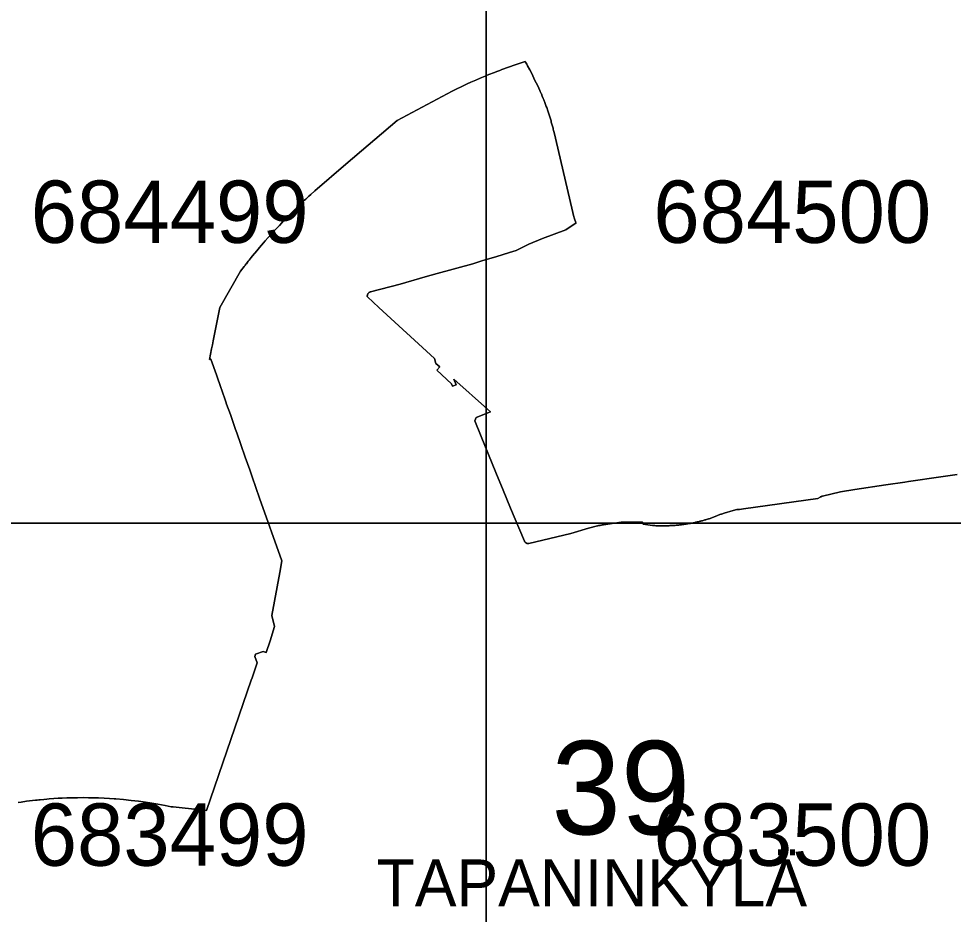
# Model space of a CAD drawing. Extents: x 25485000 to 25520000, y 6656775 to 6690000.
# Drawn here: x 25499249 to 25500750, y 6683372 to 6684810 of the extents above; entities that cross this region are included whole.
import ezdxf

# ---------------------------------------------------------------- set-up
doc = ezdxf.new("R2010")
doc.units = 0
doc.layers.add('Level 63', color=7, linetype='Continuous')

msp = doc.modelspace()

# ---------------------------------------------------------------- linework, layer by layer
at = {"layer": 'Level 63'}
for points in [[(25499000, 6684000), (25500000, 6684000), (25500000, 6685000), (25499000, 6685000)], [(25500000, 6684000), (25501000, 6684000), (25501000, 6685000), (25500000, 6685000)], [(25499000, 6683000), (25500000, 6683000), (25500000, 6684000), (25499000, 6684000)], [(25500000, 6683000), (25501000, 6683000), (25501000, 6684000), (25500000, 6684000)]]:
    msp.add_lwpolyline(points, close=True, dxfattribs=at)
for points in [[(25500756.5, 6684078.4), (25500730.4, 6684074.3), (25500678.5, 6684066.7), (25500672.5, 6684065.8), (25500641.9, 6684061.3), (25500591.9, 6684053.9), (25500569.2, 6684050.4), (25500539.9, 6684043.5), (25500539.6, 6684043.4), (25500539.4, 6684043.2), (25500539.1, 6684043.1), (25500538.9, 6684043), (25500538.6, 6684042.8), (25500538.4, 6684042.7), (25500538.1, 6684042.6), (25500537.9, 6684042.5), (25500537.6, 6684042.4), (25500537.3, 6684042.3), (25500537.1, 6684042.2), (25500536.8, 6684042.1), (25500536.5, 6684042.1), (25500536.2, 6684042), (25500532.5, 6684039.5), (25500413.5, 6684023), (25500406.8, 6684022.1), (25500402.8, 6684021.9), (25500396.5, 6684020.1), (25500382.2, 6684016), (25500380.8, 6684015.6), (25500379.5, 6684015.1), (25500378.1, 6684014.6), (25500376.8, 6684014.2), (25500375.5, 6684013.7), (25500374.2, 6684013.2), (25500372.8, 6684012.7), (25500371.5, 6684012.2), (25500370.2, 6684011.7), (25500368.9, 6684011.2), (25500367.6, 6684010.7), (25500366.2, 6684010.1), (25500364.9, 6684009.6), (25500363.6, 6684009), (25500362.2, 6684008.4), (25500360.9, 6684008), (25500359.6, 6684007.6), (25500358.2, 6684007.1), (25500356.9, 6684006.7), (25500355.5, 6684006.3), (25500354.1, 6684005.9), (25500352.8, 6684005.5), (25500351.4, 6684005.1), (25500350.1, 6684004.7), (25500348.7, 6684004.4), (25500347.3, 6684004), (25500346, 6684003.6), (25500344.6, 6684003.3), (25500343.2, 6684003), (25500341.9, 6684002.6), (25500340.5, 6684002.3), (25500339.1, 6684002), (25500337.7, 6684001.7), (25500336.3, 6684001.4), (25500335, 6684001.1), (25500333.6, 6684000.8), (25500332.2, 6684000.5), (25500330.8, 6684000.2), (25500329.4, 6684000), (25500328, 6683999.7), (25500326.6, 6683999.5), (25500325.2, 6683999.2), (25500323.8, 6683999), (25500322.4, 6683998.8), (25500321, 6683998.5), (25500319.6, 6683998.3), (25500319.1, 6683998.3), (25500317.7, 6683998.1), (25500316.3, 6683997.9), (25500314.9, 6683997.7), (25500313.5, 6683997.5), (25500312.1, 6683997.3), (25500310.6, 6683997.2), (25500309.2, 6683997), (25500307.8, 6683996.9), (25500306.4, 6683996.8), (25500305, 6683996.6), (25500303.6, 6683996.5), (25500302.2, 6683996.4), (25500300.8, 6683996.3), (25500299.4, 6683996.2), (25500298, 6683996.1), (25500296.6, 6683996), (25500295.1, 6683996), (25500293.7, 6683995.9), (25500292.3, 6683995.9), (25500290.9, 6683995.8), (25500289.5, 6683995.8), (25500288.1, 6683995.7), (25500286.7, 6683995.7), (25500285.2, 6683995.7), (25500283.8, 6683995.7), (25500282.4, 6683995.7), (25500281, 6683995.7), (25500279.6, 6683995.7), (25500278.2, 6683995.8), (25500276.8, 6683995.8), (25500275.4, 6683995.8), (25500273.9, 6683995.9), (25500272.5, 6683995.9), (25500271.1, 6683996), (25500269.7, 6683996.1), (25500268.3, 6683996.2), (25500267.2, 6683996.2), (25500252.4, 6683998.4), (25500251.1, 6684001.7), (25500243, 6684001.7), (25500233, 6684001.5), (25500217, 6684001.4), (25500188.6, 6683997.4), (25500187.5, 6683997.2), (25500186.3, 6683997.1), (25500185.2, 6683996.9), (25500184, 6683996.7), (25500182.9, 6683996.5), (25500181.7, 6683996.3), (25500180.6, 6683996.1), (25500179.5, 6683995.8), (25500178.8, 6683995.7), (25500164.1, 6683992), (25500136, 6683983.6), (25500068.5, 6683967.5), (25500068.2, 6683967.5), (25500068, 6683967.4), (25500067.8, 6683967.4), (25500067.6, 6683967.4), (25500067.4, 6683967.4), (25500067.2, 6683967.4), (25500066.9, 6683967.4), (25500066.7, 6683967.4), (25500066.5, 6683967.4), (25500066.3, 6683967.4), (25500066.1, 6683967.5), (25500065.8, 6683967.5), (25500065.6, 6683967.5), (25500065.4, 6683967.6), (25500065.2, 6683967.7), (25500065, 6683967.7), (25500064.8, 6683967.8), (25500064.6, 6683967.9), (25500064.4, 6683968), (25500064.2, 6683968.1), (25500064, 6683968.2), (25500063.8, 6683968.3), (25500063.6, 6683968.4), (25500063.5, 6683968.6), (25500063.3, 6683968.7), (25500063.1, 6683968.8), (25500063, 6683969), (25500062.8, 6683969.1), (25500062.7, 6683969.3), (25500062.5, 6683969.5), (25500062.4, 6683969.6), (25500062.2, 6683969.8), (25500062.1, 6683970), (25500062, 6683970.2), (25500061.9, 6683970.4), (25500061.8, 6683970.5), (25500061.7, 6683970.7), (25500061.6, 6683970.9), (25500061.5, 6683971.1), (25500039.3, 6684024), (25500027.5, 6684052.8), (25500015.7, 6684081.4), (25500004, 6684110.2), (25499992.2, 6684139.2), (25499981.8, 6684164.5), (25499984, 6684169.8), (25500007.1, 6684178.5), (25500002, 6684183.1), (25499947.8, 6684231.4), (25499951.6, 6684222), (25499946.1, 6684219.7), (25499944.5, 6684223.7), (25499920.8, 6684245.6), (25499925.8, 6684250.9), (25499919.2, 6684256.6), (25499916.8, 6684264.6), (25499827.8, 6684346.2), (25499809.2, 6684363.2), (25499809.2, 6684363.5), (25499809.1, 6684363.7), (25499809.1, 6684363.9), (25499809.1, 6684364.2), (25499809.1, 6684364.4), (25499809.1, 6684364.6), (25499809.1, 6684364.9), (25499809.1, 6684365.1), (25499809.1, 6684365.4), (25499809.2, 6684365.6), (25499809.2, 6684365.8), (25499809.2, 6684366.1), (25499809.3, 6684366.3), (25499809.4, 6684366.5), (25499809.4, 6684366.7), (25499809.5, 6684367), (25499809.6, 6684367.2), (25499809.7, 6684367.4), (25499809.8, 6684367.6), (25499809.9, 6684367.8), (25499810, 6684368), (25499810.1, 6684368.2), (25499810.2, 6684368.4), (25499810.4, 6684368.6), (25499810.5, 6684368.8), (25499810.7, 6684369), (25499810.8, 6684369.2), (25499811, 6684369.4), (25499811.1, 6684369.5), (25499811.3, 6684369.7), (25499811.5, 6684369.9), (25499811.7, 6684370), (25499811.8, 6684370.2), (25499812, 6684370.3), (25499812.2, 6684370.4), (25499812.4, 6684370.6), (25499812.6, 6684370.7), (25499812.8, 6684370.8), (25499813.1, 6684370.9), (25499813.3, 6684371), (25499813.5, 6684371.1), (25499813.7, 6684371.2), (25499813.9, 6684371.3), (25499814.2, 6684371.3), (25499814.3, 6684371.4), (25499861.7, 6684383.9), (25499902, 6684395.7), (25499921.2, 6684401), (25499978.6, 6684416.6), (25499994.7, 6684421.5), (25500015.4, 6684427.4), (25500037.7, 6684434.4), (25500048.2, 6684437.8), (25500068.7, 6684447.7), (25500090.3, 6684456.9), (25500127.9, 6684471.1), (25500144.7, 6684482), (25500144.4, 6684482.4), (25500144.2, 6684482.9), (25500143.9, 6684483.4), (25500143.7, 6684483.9), (25500143.5, 6684484.4), (25500143.2, 6684484.8), (25500143, 6684485.3), (25500142.8, 6684485.9), (25500142.6, 6684486.4), (25500142.4, 6684486.9), (25500142.2, 6684487.4), (25500142, 6684487.9), (25500141.9, 6684488.4), (25500141.7, 6684488.9), (25500141.5, 6684489.4), (25500141.4, 6684490), (25500141.2, 6684490.5), (25500141.1, 6684491), (25500141, 6684491.6), (25500137.6, 6684505.8), (25500109, 6684627.3), (25500108.6, 6684629), (25500108.2, 6684630.6), (25500107.8, 6684632.3), (25500107.4, 6684634), (25500106.9, 6684635.7), (25500106.5, 6684637.4), (25500106, 6684639), (25500105.6, 6684640.7), (25500105.1, 6684642.4), (25500104.6, 6684644), (25500104.2, 6684645.7), (25500103.7, 6684647.4), (25500103.2, 6684649), (25500102.7, 6684650.7), (25500102.2, 6684652.3), (25500101.6, 6684654), (25500101.1, 6684655.6), (25500100.6, 6684657.3), (25500100, 6684658.9), (25500099.5, 6684660.6), (25500098.9, 6684662.2), (25500098.4, 6684663.8), (25500097.8, 6684665.5), (25500097.2, 6684667.1), (25500096.6, 6684668.7), (25500096, 6684670.4), (25500095.4, 6684672), (25500094.8, 6684673.6), (25500094.2, 6684675.2), (25500093.6, 6684676.8), (25500093.1, 6684678), (25500093.1, 6684678.1), (25500093, 6684678.3), (25500092.6, 6684679.4), (25500091.7, 6684681.6), (25500090.1, 6684685.5), (25500088.6, 6684689.1), (25500088.2, 6684689.8), (25500088.2, 6684690), (25500086.9, 6684692.8), (25500086.1, 6684694.6), (25500082.8, 6684701.9), (25500080.2, 6684707.1), (25500077.7, 6684712), (25500073.6, 6684720.7), (25500070.2, 6684727.6), (25500066.5, 6684734.4), (25500065.1, 6684737), (25500063.4, 6684740), (25500063.3, 6684740.2), (25500063, 6684740.8), (25500062.6, 6684741.4), (25500046.3, 6684735.6), (25500025.2, 6684728.2), (25500021.9, 6684726.9), (25500018.8, 6684725.8), (25500011.6, 6684723), (25500005.8, 6684720.7), (25500001.8, 6684719), (25499998.2, 6684717.5), (25499990.3, 6684714.3), (25499983.6, 6684711.4), (25499977.9, 6684708.9), (25499975.4, 6684707.8), (25499969.7, 6684705.2), (25499960.7, 6684701.1), (25499951.9, 6684696.9), (25499945.3, 6684693.7), (25499857.1, 6684646.6), (25499774.7, 6684576.3), (25499724.7, 6684533.7), (25499718.4, 6684527.9), (25499715.3, 6684525), (25499715.3, 6684525), (25499715.3, 6684525), (25499715.3, 6684525), (25499714.9, 6684524.6), (25499714.7, 6684524.5), (25499714.5, 6684524.3), (25499714.4, 6684524.2), (25499714.3, 6684524.1), (25499713.9, 6684523.7), (25499713.8, 6684523.6), (25499713.5, 6684523.3), (25499713.1, 6684523), (25499712.6, 6684522.5), (25499712.1, 6684522), (25499711.3, 6684521.3), (25499710.2, 6684520.2), (25499708.1, 6684518.3), (25499701.5, 6684512), (25499700.3, 6684510.7), (25499698.4, 6684509), (25499690, 6684500.7), (25499680.6, 6684491.3), (25499674.7, 6684485.3), (25499671.7, 6684482.2), (25499667.9, 6684478.1), (25499665.3, 6684475.4), (25499660.4, 6684470.2), (25499654.9, 6684464.2), (25499649.8, 6684458.6), (25499645, 6684453.4), (25499642.1, 6684450.1), (25499635.7, 6684442.6), (25499631.4, 6684437.3), (25499624.7, 6684429), (25499622.5, 6684426.3), (25499619.1, 6684422), (25499618.9, 6684421.7), (25499618.5, 6684421.3), (25499617.9, 6684420.5), (25499616.9, 6684419.1), (25499614.9, 6684416.6), (25499614.9, 6684416.6), (25499614.8, 6684416.5), (25499614.8, 6684416.5), (25499614.8, 6684416.5), (25499614.8, 6684416.4), (25499614.7, 6684416.4), (25499614.7, 6684416.3), (25499614.5, 6684416.1), (25499613.1, 6684414.3), (25499612.7, 6684413.8), (25499612, 6684412.8), (25499611.4, 6684412.1), (25499605.6, 6684404.4), (25499572, 6684346.5), (25499561.6, 6684292.8), (25499560.3, 6684286.1), (25499559.1, 6684279.8), (25499555.8, 6684262.8), (25499557.9, 6684263.4), (25499566.8, 6684238.3), (25499574.5, 6684216.1), (25499574.8, 6684215.1), (25499582, 6684194.7), (25499583.2, 6684191.1), (25499589.1, 6684174.2), (25499591.8, 6684166.3), (25499597.5, 6684150.4), (25499599.4, 6684145), (25499605.9, 6684126.1), (25499612.8, 6684106.2), (25499620.2, 6684085.4), (25499624, 6684074.6), (25499636.1, 6684040.1), (25499671.7, 6683939.4), (25499668.4, 6683920.6), (25499656, 6683851.6), (25499660.2, 6683834.1), (25499652.9, 6683811.3), (25499646.4, 6683792.5), (25499641.7, 6683794.1), (25499629.7, 6683789.6), (25499628.4, 6683785.8), (25499632.1, 6683775.9), (25499624.1, 6683751.8), (25499622.6, 6683747.7), (25499550.7, 6683538.5), (25499541.2, 6683539.6), (25499497.1, 6683544.7), (25499493.9, 6683544.8), (25499484.4, 6683546.7), (25499472.9, 6683548.8), (25499462.9, 6683550.5), (25499452.7, 6683552.1), (25499441.7, 6683553.6), (25499429.7, 6683555), (25499417.3, 6683556.3), (25499405.4, 6683557.3), (25499402.3, 6683557.5), (25499395.1, 6683558), (25499386.7, 6683558.5), (25499377.1, 6683558.9), (25499369, 6683559.2), (25499361.5, 6683559.3), (25499353.5, 6683559.4), (25499343.9, 6683559.3), (25499334.9, 6683559.2), (25499330.8, 6683559), (25499326.7, 6683558.9), (25499319.2, 6683558.6), (25499312.6, 6683558.3), (25499305.5, 6683557.8), (25499298, 6683557.3), (25499294.5, 6683557), (25499289.8, 6683556.6), (25499283.8, 6683556), (25499281.7, 6683555.8), (25499278.9, 6683555.5), (25499276.3, 6683555.3), (25499261.8, 6683553.5), (25499253, 6683552.3), (25499248.3, 6683551.6)], [(25499248.3, 6683551.6), (25499253, 6683552.3), (25499261.8, 6683553.5), (25499276.3, 6683555.3), (25499278.9, 6683555.5), (25499281.7, 6683555.8), (25499283.8, 6683556), (25499289.8, 6683556.6), (25499294.5, 6683557), (25499298, 6683557.3), (25499305.5, 6683557.8), (25499312.6, 6683558.3), (25499319.2, 6683558.6), (25499326.7, 6683558.9), (25499330.8, 6683559), (25499334.9, 6683559.2), (25499343.9, 6683559.3), (25499353.5, 6683559.4), (25499361.5, 6683559.3), (25499369, 6683559.2), (25499377.1, 6683558.9), (25499386.7, 6683558.5), (25499395.1, 6683558), (25499402.3, 6683557.5), (25499405.4, 6683557.3), (25499417.3, 6683556.3), (25499429.7, 6683555), (25499441.7, 6683553.6), (25499452.7, 6683552.1), (25499462.9, 6683550.5), (25499472.9, 6683548.8), (25499484.4, 6683546.7), (25499493.9, 6683544.8), (25499497.1, 6683544.7), (25499541.2, 6683539.6), (25499550.7, 6683538.5), (25499622.6, 6683747.7), (25499624.1, 6683751.8), (25499632.1, 6683775.9), (25499628.4, 6683785.8), (25499629.7, 6683789.6), (25499641.7, 6683794.1), (25499646.4, 6683792.5), (25499652.9, 6683811.3), (25499660.2, 6683834.1), (25499656, 6683851.6), (25499668.4, 6683920.6), (25499671.7, 6683939.4), (25499636.1, 6684040.1), (25499624, 6684074.6), (25499620.2, 6684085.4), (25499612.8, 6684106.2), (25499605.9, 6684126.1), (25499599.4, 6684145), (25499597.5, 6684150.4), (25499591.8, 6684166.3), (25499589.1, 6684174.2), (25499583.2, 6684191.1), (25499582, 6684194.7), (25499574.8, 6684215.1), (25499574.5, 6684216.1), (25499566.8, 6684238.3), (25499557.9, 6684263.4), (25499555.8, 6684262.8), (25499559.1, 6684279.8), (25499560.3, 6684286.1), (25499561.6, 6684292.8), (25499572, 6684346.5), (25499605.6, 6684404.4), (25499611.4, 6684412.1), (25499612, 6684412.8), (25499612.7, 6684413.8), (25499613.1, 6684414.3), (25499614.5, 6684416.1), (25499614.7, 6684416.3), (25499614.7, 6684416.4), (25499614.8, 6684416.4), (25499614.8, 6684416.5), (25499614.8, 6684416.5), (25499614.8, 6684416.5), (25499614.9, 6684416.6), (25499614.9, 6684416.6), (25499616.9, 6684419.1), (25499617.9, 6684420.5), (25499618.5, 6684421.3), (25499618.9, 6684421.7), (25499619.1, 6684422), (25499622.5, 6684426.3), (25499624.7, 6684429), (25499631.4, 6684437.3), (25499635.7, 6684442.6), (25499642.1, 6684450.1), (25499645, 6684453.4), (25499649.8, 6684458.6), (25499654.9, 6684464.2), (25499660.4, 6684470.2), (25499665.3, 6684475.4), (25499667.9, 6684478.1), (25499671.7, 6684482.2), (25499674.7, 6684485.3), (25499680.6, 6684491.3), (25499690, 6684500.7), (25499698.4, 6684509), (25499700.3, 6684510.7), (25499701.5, 6684512), (25499708.1, 6684518.3), (25499710.2, 6684520.2), (25499711.3, 6684521.3), (25499712.1, 6684522), (25499712.6, 6684522.5), (25499713.1, 6684523), (25499713.5, 6684523.3), (25499713.8, 6684523.6), (25499713.9, 6684523.7), (25499714.3, 6684524.1), (25499714.4, 6684524.2), (25499714.5, 6684524.3), (25499714.7, 6684524.5), (25499714.9, 6684524.6), (25499715.3, 6684525), (25499715.3, 6684525), (25499715.3, 6684525), (25499715.3, 6684525), (25499718.4, 6684527.9), (25499724.7, 6684533.7), (25499774.7, 6684576.3), (25499857.1, 6684646.6), (25499945.3, 6684693.7), (25499951.9, 6684696.9), (25499960.7, 6684701.1), (25499969.7, 6684705.2), (25499975.4, 6684707.8), (25499977.9, 6684708.9), (25499983.6, 6684711.4), (25499990.3, 6684714.3), (25499998.2, 6684717.5), (25500001.8, 6684719), (25500005.8, 6684720.7), (25500011.6, 6684723), (25500018.8, 6684725.8), (25500021.9, 6684726.9), (25500025.2, 6684728.2), (25500046.3, 6684735.6), (25500062.6, 6684741.4), (25500063, 6684740.8), (25500063.3, 6684740.2), (25500063.4, 6684740), (25500065.1, 6684737), (25500066.5, 6684734.4), (25500070.2, 6684727.6), (25500073.6, 6684720.7), (25500077.7, 6684712), (25500080.2, 6684707.1), (25500082.8, 6684701.9), (25500086.1, 6684694.6), (25500086.9, 6684692.8), (25500088.2, 6684690), (25500088.2, 6684689.8), (25500088.6, 6684689.1), (25500090.1, 6684685.5), (25500091.7, 6684681.6), (25500092.6, 6684679.4), (25500093, 6684678.3), (25500093.1, 6684678.1), (25500093.1, 6684678), (25500093.6, 6684676.8), (25500094.2, 6684675.2), (25500094.8, 6684673.6), (25500095.4, 6684672), (25500096, 6684670.4), (25500096.6, 6684668.7), (25500097.2, 6684667.1), (25500097.8, 6684665.5), (25500098.4, 6684663.8), (25500098.9, 6684662.2), (25500099.5, 6684660.6), (25500100, 6684658.9), (25500100.6, 6684657.3), (25500101.1, 6684655.6), (25500101.6, 6684654), (25500102.2, 6684652.3), (25500102.7, 6684650.7), (25500103.2, 6684649), (25500103.7, 6684647.4), (25500104.2, 6684645.7), (25500104.6, 6684644), (25500105.1, 6684642.4), (25500105.6, 6684640.7), (25500106, 6684639), (25500106.5, 6684637.4), (25500106.9, 6684635.7), (25500107.4, 6684634), (25500107.8, 6684632.3), (25500108.2, 6684630.6), (25500108.6, 6684629), (25500109, 6684627.3), (25500137.6, 6684505.8), (25500141, 6684491.6), (25500141.1, 6684491), (25500141.2, 6684490.5), (25500141.4, 6684490), (25500141.5, 6684489.4), (25500141.7, 6684488.9), (25500141.9, 6684488.4), (25500142, 6684487.9), (25500142.2, 6684487.4), (25500142.4, 6684486.9), (25500142.6, 6684486.4), (25500142.8, 6684485.9), (25500143, 6684485.3), (25500143.2, 6684484.8), (25500143.5, 6684484.4), (25500143.7, 6684483.9), (25500143.9, 6684483.4), (25500144.2, 6684482.9), (25500144.4, 6684482.4), (25500144.7, 6684482), (25500127.9, 6684471.1), (25500090.3, 6684456.9), (25500068.7, 6684447.7), (25500048.2, 6684437.8), (25500037.7, 6684434.4), (25500015.4, 6684427.4), (25499994.7, 6684421.5), (25499978.6, 6684416.6), (25499921.2, 6684401), (25499902, 6684395.7), (25499861.7, 6684383.9), (25499814.3, 6684371.4), (25499814.2, 6684371.3), (25499813.9, 6684371.3), (25499813.7, 6684371.2), (25499813.5, 6684371.1), (25499813.3, 6684371), (25499813.1, 6684370.9), (25499812.8, 6684370.8), (25499812.6, 6684370.7), (25499812.4, 6684370.6), (25499812.2, 6684370.4), (25499812, 6684370.3), (25499811.8, 6684370.2), (25499811.7, 6684370), (25499811.5, 6684369.9), (25499811.3, 6684369.7), (25499811.1, 6684369.5), (25499811, 6684369.4), (25499810.8, 6684369.2), (25499810.7, 6684369), (25499810.5, 6684368.8), (25499810.4, 6684368.6), (25499810.2, 6684368.4), (25499810.1, 6684368.2), (25499810, 6684368), (25499809.9, 6684367.8), (25499809.8, 6684367.6), (25499809.7, 6684367.4), (25499809.6, 6684367.2), (25499809.5, 6684367), (25499809.4, 6684366.7), (25499809.4, 6684366.5), (25499809.3, 6684366.3), (25499809.2, 6684366.1), (25499809.2, 6684365.8), (25499809.2, 6684365.6), (25499809.1, 6684365.4), (25499809.1, 6684365.1), (25499809.1, 6684364.9), (25499809.1, 6684364.6), (25499809.1, 6684364.4), (25499809.1, 6684364.2), (25499809.1, 6684363.9), (25499809.1, 6684363.7), (25499809.2, 6684363.5), (25499809.2, 6684363.2), (25499827.8, 6684346.2), (25499916.8, 6684264.6), (25499919.2, 6684256.6), (25499925.8, 6684250.9), (25499920.8, 6684245.6), (25499944.5, 6684223.7), (25499946.1, 6684219.7), (25499951.6, 6684222), (25499947.8, 6684231.4), (25500002, 6684183.1), (25500007.1, 6684178.5), (25499984, 6684169.8), (25499981.8, 6684164.5), (25499992.2, 6684139.2), (25500004, 6684110.2), (25500015.7, 6684081.4), (25500027.5, 6684052.8), (25500039.3, 6684024), (25500061.5, 6683971.1), (25500061.6, 6683970.9), (25500061.7, 6683970.7), (25500061.8, 6683970.5), (25500061.9, 6683970.4), (25500062, 6683970.2), (25500062.1, 6683970), (25500062.2, 6683969.8), (25500062.4, 6683969.6), (25500062.5, 6683969.5), (25500062.7, 6683969.3), (25500062.8, 6683969.1), (25500063, 6683969), (25500063.1, 6683968.8), (25500063.3, 6683968.7), (25500063.5, 6683968.6), (25500063.6, 6683968.4), (25500063.8, 6683968.3), (25500064, 6683968.2), (25500064.2, 6683968.1), (25500064.4, 6683968), (25500064.6, 6683967.9), (25500064.8, 6683967.8), (25500065, 6683967.7), (25500065.2, 6683967.7), (25500065.4, 6683967.6), (25500065.6, 6683967.5), (25500065.8, 6683967.5), (25500066.1, 6683967.5), (25500066.3, 6683967.4), (25500066.5, 6683967.4), (25500066.7, 6683967.4), (25500066.9, 6683967.4), (25500067.2, 6683967.4), (25500067.4, 6683967.4), (25500067.6, 6683967.4), (25500067.8, 6683967.4), (25500068, 6683967.4), (25500068.2, 6683967.5), (25500068.5, 6683967.5), (25500136, 6683983.6), (25500164.1, 6683992), (25500178.8, 6683995.7), (25500179.5, 6683995.8), (25500180.6, 6683996.1), (25500181.7, 6683996.3), (25500182.9, 6683996.5), (25500184, 6683996.7), (25500185.2, 6683996.9), (25500186.3, 6683997.1), (25500187.5, 6683997.2), (25500188.6, 6683997.4), (25500217, 6684001.4), (25500233, 6684001.5), (25500243, 6684001.7), (25500251.1, 6684001.7), (25500252.4, 6683998.4), (25500267.2, 6683996.2), (25500268.3, 6683996.2), (25500269.7, 6683996.1), (25500271.1, 6683996), (25500272.5, 6683995.9), (25500273.9, 6683995.9), (25500275.4, 6683995.8), (25500276.8, 6683995.8), (25500278.2, 6683995.8), (25500279.6, 6683995.7), (25500281, 6683995.7), (25500282.4, 6683995.7), (25500283.8, 6683995.7), (25500285.2, 6683995.7), (25500286.7, 6683995.7), (25500288.1, 6683995.7), (25500289.5, 6683995.8), (25500290.9, 6683995.8), (25500292.3, 6683995.9), (25500293.7, 6683995.9), (25500295.1, 6683996), (25500296.6, 6683996), (25500298, 6683996.1), (25500299.4, 6683996.2), (25500300.8, 6683996.3), (25500302.2, 6683996.4), (25500303.6, 6683996.5), (25500305, 6683996.6), (25500306.4, 6683996.8), (25500307.8, 6683996.9), (25500309.2, 6683997), (25500310.6, 6683997.2), (25500312.1, 6683997.3), (25500313.5, 6683997.5), (25500314.9, 6683997.7), (25500316.3, 6683997.9), (25500317.7, 6683998.1), (25500319.1, 6683998.3), (25500319.6, 6683998.3), (25500321, 6683998.5), (25500322.4, 6683998.8), (25500323.8, 6683999), (25500325.2, 6683999.2), (25500326.6, 6683999.5), (25500328, 6683999.7), (25500329.4, 6684000), (25500330.8, 6684000.2), (25500332.2, 6684000.5), (25500333.6, 6684000.8), (25500335, 6684001.1), (25500336.3, 6684001.4), (25500337.7, 6684001.7), (25500339.1, 6684002), (25500340.5, 6684002.3), (25500341.9, 6684002.6), (25500343.2, 6684003), (25500344.6, 6684003.3), (25500346, 6684003.6), (25500347.3, 6684004), (25500348.7, 6684004.4), (25500350.1, 6684004.7), (25500351.4, 6684005.1), (25500352.8, 6684005.5), (25500354.1, 6684005.9), (25500355.5, 6684006.3), (25500356.9, 6684006.7), (25500358.2, 6684007.1), (25500359.6, 6684007.6), (25500360.9, 6684008), (25500362.2, 6684008.4), (25500363.6, 6684009), (25500364.9, 6684009.6), (25500366.2, 6684010.1), (25500367.6, 6684010.7), (25500368.9, 6684011.2), (25500370.2, 6684011.7), (25500371.5, 6684012.2), (25500372.8, 6684012.7), (25500374.2, 6684013.2), (25500375.5, 6684013.7), (25500376.8, 6684014.2), (25500378.1, 6684014.6), (25500379.5, 6684015.1), (25500380.8, 6684015.6), (25500382.2, 6684016), (25500396.5, 6684020.1), (25500402.8, 6684021.9), (25500406.8, 6684022.1), (25500413.5, 6684023), (25500532.5, 6684039.5), (25500536.2, 6684042), (25500536.5, 6684042.1), (25500536.8, 6684042.1), (25500537.1, 6684042.2), (25500537.3, 6684042.3), (25500537.6, 6684042.4), (25500537.9, 6684042.5), (25500538.1, 6684042.6), (25500538.4, 6684042.7), (25500538.6, 6684042.8), (25500538.9, 6684043), (25500539.1, 6684043.1), (25500539.4, 6684043.2), (25500539.6, 6684043.4), (25500539.9, 6684043.5), (25500569.2, 6684050.4), (25500591.9, 6684053.9), (25500641.9, 6684061.3), (25500672.5, 6684065.8), (25500678.5, 6684066.7), (25500730.4, 6684074.3), (25500756.5, 6684078.4)]]:
    msp.add_lwpolyline(points, dxfattribs=at)

# ---------------------------------------------------------------- texts
for s, height, p in [('684499', 100, (25499268.5, 6684450)), ('684500', 100, (25500268.5, 6684450)), ('39', 150, (25500104.7, 6683500.4)), ('683499', 100, (25499268.5, 6683450)), ('683500', 100, (25500268.5, 6683450)), ('TAPANINKYLÄ', 75, (25499824.2, 6683385.1))]:
    msp.add_text(s, height=height, dxfattribs=at).set_placement(p)

doc.saveas('drawing.dxf')
